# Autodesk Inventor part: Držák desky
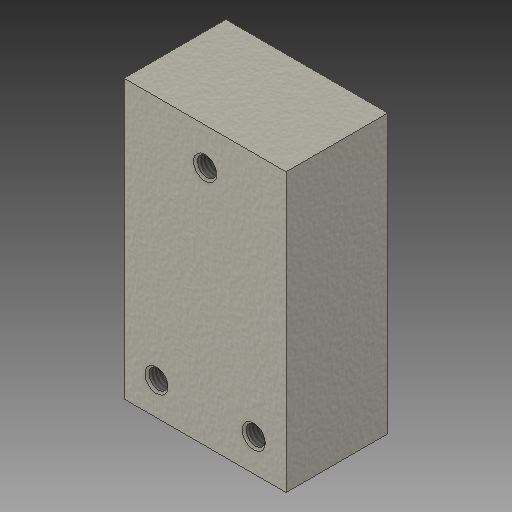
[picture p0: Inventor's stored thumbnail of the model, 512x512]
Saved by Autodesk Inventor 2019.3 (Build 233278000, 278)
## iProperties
Created: 2019-02
Part Number: Držák desky
Material: Ocel, měkká, svařovaná
Document SubType Name: Modeling
Designer: B-hon
Density: 7.85 g/cm^3
Appearance: Ocel – litá
Author: B-hon
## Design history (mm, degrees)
sketch "Náčrt1"
  geometry: L1 (17.5, -30)-(-17.5, -30); L2 (-17.5, -30)-(-17.5, 30); L3 (-17.5, 30)-(17.5, 30); L4 (17.5, 30)-(17.5, -30); L5 (17.5, -30)-(-17.5, 30); L6 (-17.5, -30)-(17.5, 30); 1 further point
  constraints: 12 end point, 2 midpoint, 2 parallel, 1 horizontal, 1 perpendicular
  dimensions: "d0" = 35 distance of L2.end L3.end; "d1" = 60 distance of L1.end L2.end
extrude "Vysunutí1" new body sketch "Náčrt1" distance "d2" = 22; taper "d3" = 0 deg
sketch "Náčrt2"
  geometry: L1 (-17.5, -30)-(17.5, -30) reference; L2 (17.5, -30)-(17.5, 30) reference; 4 further points
  constraints: 1 horizontal alignment
  dimensions: "d4" = 21 distance of point (-10.5, -23) point (10.5, -23); "d5" = 7 distance from line of L1 point (-10.5, -23); "d6" = 7 distance from line of L2 point (10.5, -23); "d7" = 10.5 horizontal distance of point (10.5, -23) point (0, 22) (= 0.5 x d4); "d8" = 52 distance from line of L1 point (0, 22)
hole "Díra1" sketch "Náčrt2" at (10.5, -23), (-10.5, -23), (0, 22) diameter "d9" = 4.134; stored, may be unused: countersink angle "d13" = 90 deg, drill point angle "d15" = 118 deg; dims "d10" = 10, "d11" = 5, "d12" = 2, "d14" = 14.2
node "Těleso1"
